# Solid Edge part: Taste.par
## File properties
Author: Heike
Template: Normal.par
Last saved by: Heike
Revision: 19
Application: Solid Edge
Dichte: 1,190 kg/dm^3
Genauigkeit: 0,990
Material: Acryl
Teilflächenrmatvorlage: Orange
Füllformatvorlage: ANSI34(Plastic)
Virtuelle Formatvorlage: Klarer, ionomer Harz
Coef. of Thermal Exp: 7.2e-05
Thermal Conductivity: 2.5
Specific Heat: 0.0
Modulus of Elasticity: 1930531960.0
Poission's Ratio: 0.4
Yield Stress: 37921163.5
Ultimate Stress: 0.0
Elongation: 0.0
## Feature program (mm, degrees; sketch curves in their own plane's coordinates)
sketch for "unnamed Protrusion 1" plane through (0, 0, 0) normal (0, 0, 1) x-axis (1, 0, 0)
  line (-20, 20) -> (20, 20)
  line (20, 20) -> (20, -20)
  line (20, -20) -> (-20, -20)
  line (-20, -20) -> (-20, 20)
  dimension (linear) = 20
extrude "unnamed Protrusion 1" add finite 7 along +normal
fillet "Ausrundung" radius 2
chamfer "Fase" setback 1
thinwall "Dünnwand"  Thickness = 1 mm
sketch for "Zylinder" #1 plane through (0, 0, 1) normal (0, 0, 1) x-axis (-1, 0, 0)
sketch for "Zylinder" #2 plane through (0, 0, 1) normal (0, 0, 1) x-axis (-1, 0, 0)
  circle centre (0, 0) radius 3.1
extrude "Zylinder" add finite 3.5 along +normal
chamfer "Fase_3" setback 0.3
logasc func "Lippe"  LipOrGrooveWidth = 1 mm; LipOrGrooveHeight = 1 mm
chamfer "Fase1" setback 1
sketch for "LED" plane through (0, 0, 1) normal (0, 0, 1) x-axis (1, 0, 0)
  circle centre (0, 14.605) radius 1.5
extrude "LED" cut finite 0.6 along -normal
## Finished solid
Body 1: solid body, 80 faces, 176 edges, 100 vertices.
  Faces by surface: plane 54, cone 16, cylinder 10
  Edges by curve: line 140, circle 36
Bounding box of the edges (mm): 42.000 x 42.000 x 7.000, from (-21, -21, 0) to (21, 21, 7).
Cylindrical faces by radius (mm): R1 x4, R1.5 x1, R2 x4, R3.1 x1
Conical faces (half-angle, radius in mm at the cone's reference point): 45 deg R0.2929 x4, 45 deg R1 x8, 45 deg R2 x4
Planar faces by outward normal: +x 5, +y 5, +z 5, -x 5, -y 5, -z 1, oblique 28
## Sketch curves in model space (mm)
line (57, 0, 0) -> (-57, 0, 0)
line (8, 8, 0) -> (8, -8, 0)
line (8, -8, 0) -> (-8, -8, 0)
line (-8, -8, 0) -> (-8, 8, 0)
line (-8, 8, 0) -> (8, 8, 0)
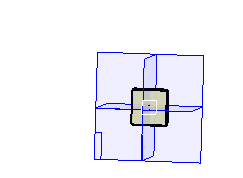
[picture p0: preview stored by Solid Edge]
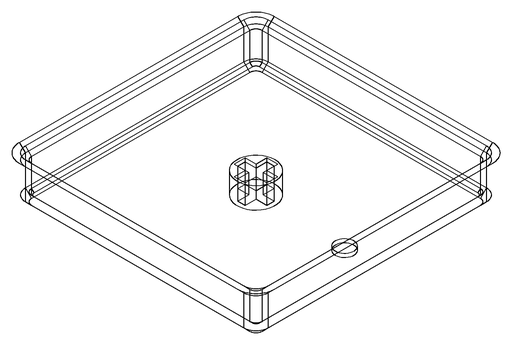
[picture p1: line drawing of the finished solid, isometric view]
